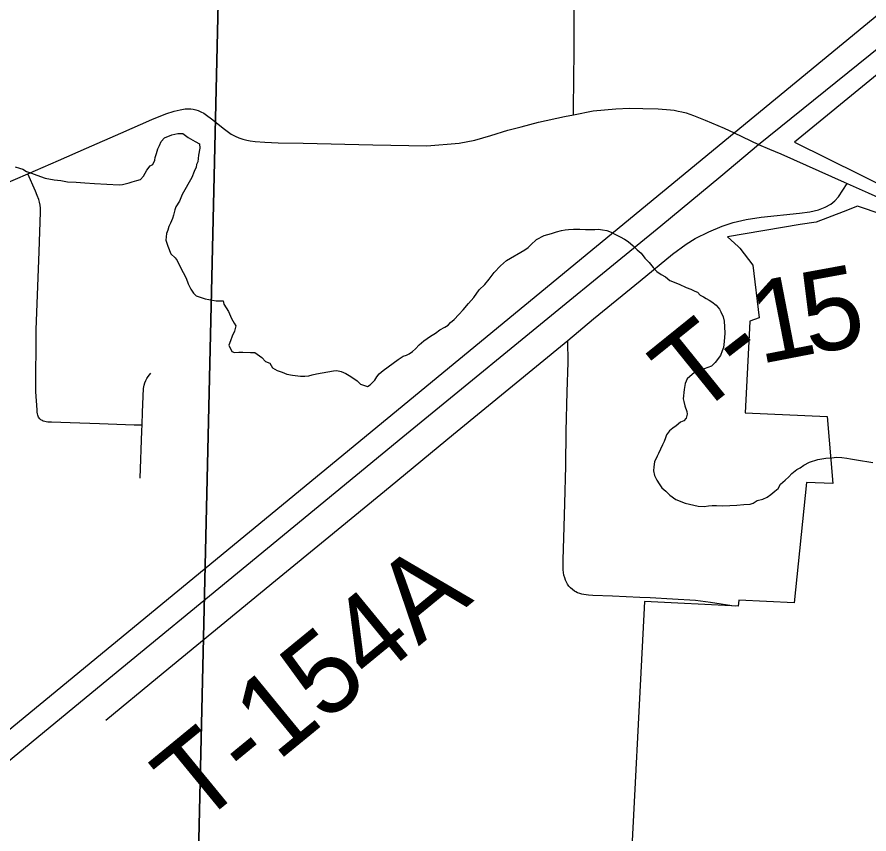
# Model space of a CAD drawing. Extents: x 2.4 to 73.1, y 4.5 to 25.6.
# Drawn here: x 34.9914 to 35.2878, y 22.6553 to 22.9395 of the extents above; entities that cross this region are included whole.
import ezdxf

# ---------------------------------------------------------------- set-up
doc = ezdxf.new("R2010")
doc.units = 0
for name, color, linetype in [('GM_X_Corporation', 7, 'Continuous'), ('GM_X_Minor_River', 7, 'Continuous'), ('GM_X_Section', 7, 'Continuous'), ('GM_X_Township_Road', 7, 'Continuous'), ('GM_X_Township_Road_Text', 7, 'Continuous'), ('GM_X_US_Route', 7, 'Continuous')]:
    doc.layers.add(name, color=color, linetype=linetype)

msp = doc.modelspace()

# ---------------------------------------------------------------- linework, layer by layer
at = {"layer": 'GM_X_Corporation'}
for points in [[(35.29059, 22.91944), (35.26186, 22.89598), (35.33054, 22.86195)], [(35.30132, 22.86774), (35.28377, 22.87371), (35.27879, 22.87177), (35.2694, 22.86809), (35.26388, 22.86727), (35.23852, 22.86307), (35.24226, 22.85961), (35.24281, 22.85911), (35.24742, 22.85311), (35.24962, 22.83487), (35.24632, 22.83373), (35.24607, 22.82887), (35.24471, 22.8018), (35.27327, 22.80056), (35.27521, 22.77718), (35.26598, 22.77751), (35.26172, 22.73566), (35.24248, 22.73661), (35.2423, 22.73449), (35.20964, 22.73611), (35.20424, 22.63033)]]:
    msp.add_lwpolyline(points, dxfattribs=at)
at = {"layer": 'GM_X_Minor_River'}
for points in [[(35.01841, 22.88152), (35.02695, 22.88112), (35.02809, 22.88128), (35.02905, 22.88144), (35.03038, 22.88179), (35.03153, 22.88214), (35.03307, 22.88267), (35.0344, 22.88302), (35.03538, 22.88413), (35.03657, 22.88619), (35.03775, 22.88768), (35.03871, 22.88822), (35.03932, 22.88973), (35.03953, 22.89067), (35.03995, 22.89199), (35.04037, 22.89369), (35.04097, 22.89481), (35.04157, 22.89613), (35.04274, 22.89743), (35.04524, 22.8985), (35.04734, 22.89902), (35.04905, 22.89898), (35.05091, 22.8976), (35.05335, 22.89621), (35.05485, 22.89541), (35.055, 22.89389), (35.05456, 22.89143), (35.05431, 22.88916), (35.05391, 22.88822), (35.05369, 22.88728), (35.05308, 22.88577), (35.05227, 22.8837), (35.04889, 22.87771), (35.04789, 22.87546), (35.0467, 22.8734), (35.04629, 22.87246), (35.04587, 22.87057), (35.04546, 22.86944), (35.04485, 22.86775), (35.04425, 22.86663), (35.04383, 22.86531), (35.04343, 22.86418), (35.04318, 22.86191), (35.04389, 22.8598), (35.04496, 22.85711), (35.04644, 22.85575), (35.04718, 22.85478), (35.0479, 22.85305), (35.04916, 22.85055), (35.05025, 22.84862), (35.05097, 22.84671), (35.05187, 22.84479), (35.05278, 22.84343), (35.05371, 22.84246), (35.05691, 22.84143), (35.06069, 22.84076), (35.06316, 22.8407), (35.06332, 22.83956), (35.06497, 22.83705), (35.06605, 22.83455), (35.06696, 22.83301), (35.0675, 22.83205), (35.06707, 22.83016), (35.06627, 22.82847), (35.06566, 22.82678), (35.06505, 22.82527), (35.06614, 22.82316), (35.06708, 22.82275), (35.0686, 22.8229), (35.06993, 22.82287), (35.07259, 22.8228), (35.07411, 22.82276), (35.07653, 22.82099), (35.07783, 22.81963), (35.07933, 22.81902), (35.08024, 22.81748), (35.08193, 22.81649), (35.08362, 22.81588), (35.08532, 22.81526), (35.0872, 22.81484), (35.09005, 22.81457), (35.09156, 22.81454), (35.0929, 22.81469), (35.09405, 22.81504), (35.09557, 22.81538), (35.10149, 22.81637), (35.10263, 22.81653), (35.10414, 22.81612), (35.10583, 22.8155), (35.10695, 22.81472), (35.10826, 22.81392), (35.10976, 22.81294), (35.11087, 22.81177), (35.11332, 22.81095), (35.11428, 22.81149), (35.11584, 22.81316), (35.11663, 22.81428), (35.11742, 22.8154), (35.11877, 22.81651), (35.12051, 22.81779), (35.12226, 22.81907)], [(34.99083, 22.88735), (34.99234, 22.88693), (34.99347, 22.88652), (34.99478, 22.88573), (34.99647, 22.88512), (34.99835, 22.8845), (35.00118, 22.88348), (35.00439, 22.88283), (35.00666, 22.88258), (35.00893, 22.88214), (35.01197, 22.88207), (35.015, 22.8818), (35.01841, 22.88152)], [(35.12226, 22.81907), (35.124, 22.82036), (35.12574, 22.82146), (35.12688, 22.82181), (35.12785, 22.82235), (35.129, 22.82308), (35.12998, 22.82401), (35.13134, 22.82549), (35.1329, 22.82678), (35.13522, 22.82843), (35.13695, 22.82953), (35.1385, 22.83063), (35.14023, 22.83153), (35.14139, 22.83226), (35.14217, 22.83319), (35.14353, 22.8343), (35.14509, 22.83597), (35.14665, 22.83764), (35.14842, 22.83987), (35.15037, 22.84191), (35.15214, 22.84453), (35.15409, 22.84638), (35.15566, 22.84823), (35.15743, 22.85066), (35.15957, 22.85288), (35.16171, 22.85473), (35.16807, 22.85855), (35.16923, 22.85928), (35.1702, 22.86021), (35.17215, 22.86206), (35.17484, 22.86351), (35.17733, 22.86421), (35.17905, 22.86473), (35.18077, 22.86526), (35.18211, 22.86541), (35.18325, 22.86558), (35.18496, 22.86572), (35.18724, 22.86566), (35.18914, 22.86562), (35.19104, 22.86557), (35.19237, 22.86554), (35.1937, 22.86569), (35.19502, 22.86547), (35.19654, 22.86524), (35.19804, 22.86463), (35.19954, 22.86383), (35.20123, 22.86303), (35.20273, 22.86223), (35.20404, 22.86144), (35.20571, 22.85988), (35.20719, 22.85851), (35.2085, 22.85734), (35.20978, 22.8556), (35.21126, 22.85404), (35.21274, 22.8523), (35.21403, 22.85093), (35.21553, 22.84995), (35.21703, 22.84915), (35.21851, 22.84778), (35.22171, 22.84656), (35.22415, 22.84536), (35.22584, 22.84475), (35.22716, 22.84415), (35.2281, 22.84374), (35.22902, 22.84277), (35.23015, 22.84217), (35.23108, 22.84158), (35.23221, 22.84098), (35.23314, 22.84039), (35.23463, 22.83921), (35.23574, 22.83785), (35.23628, 22.83689), (35.237, 22.83516), (35.23734, 22.83363), (35.23748, 22.83173), (35.23762, 22.82945), (35.23735, 22.82661), (35.23711, 22.82452), (35.2367, 22.82339), (35.23609, 22.8217), (35.23432, 22.81928), (35.23296, 22.81798), (35.23047, 22.8171), (35.22855, 22.81638), (35.22702, 22.81585), (35.22449, 22.81364), (35.22388, 22.81195), (35.22345, 22.80987), (35.22318, 22.80665), (35.22334, 22.80569), (35.22369, 22.80416), (35.2244, 22.80225), (35.22456, 22.80129), (35.22415, 22.79997), (35.22337, 22.79904), (35.22221, 22.7985), (35.22066, 22.79721), (35.21951, 22.79648), (35.21834, 22.79556), (35.21735, 22.79407), (35.21695, 22.79313)], [(35.21695, 22.79313), (35.21654, 22.79181), (35.21594, 22.79069), (35.21454, 22.78768), (35.21413, 22.78675), (35.21313, 22.78468), (35.2129, 22.78298), (35.21287, 22.78165), (35.2132, 22.77993), (35.21392, 22.77839), (35.21484, 22.77704), (35.21576, 22.77569), (35.21705, 22.77452), (35.21854, 22.77315), (35.22059, 22.77158), (35.22379, 22.77036), (35.22832, 22.76929), (35.23041, 22.76924), (35.23193, 22.76939), (35.23326, 22.76955), (35.23478, 22.76951), (35.23687, 22.76946), (35.23934, 22.76958), (35.24182, 22.76971), (35.24429, 22.76984), (35.24638, 22.76998), (35.24753, 22.77033), (35.24888, 22.77124), (35.25079, 22.77176), (35.25233, 22.77249), (35.25368, 22.7734), (35.25504, 22.7745), (35.2562, 22.77542), (35.257, 22.77692), (35.25856, 22.7784), (35.25992, 22.77951), (35.26089, 22.78062), (35.26264, 22.7821), (35.26379, 22.78264), (35.26514, 22.78355), (35.26707, 22.78465), (35.26994, 22.78552), (35.2728, 22.78602), (35.2749, 22.78616), (35.27642, 22.78631), (35.27832, 22.78626), (35.28002, 22.78603), (35.28134, 22.7858), (35.28342, 22.78537), (35.2891, 22.78447)]]:
    msp.add_lwpolyline(points, dxfattribs=at)
at = {"layer": 'GM_X_Section'}
for points in [[(34.56162, 23.09756), (35.06465, 23.08503), (35.0531, 22.5831), (34.54832, 22.60211)], [(35.06465, 23.08503), (35.56221, 23.08304), (35.55168, 22.57541), (35.0531, 22.5831)]]:
    msp.add_lwpolyline(points, close=True, dxfattribs=at)
at = {"layer": 'GM_X_Township_Road'}
for points in [[(35.18506, 22.91682), (35.18518, 22.92862), (35.18525, 22.96188), (35.18557, 23.00166), (35.18574, 23.0119), (35.186, 23.01653), (35.18634, 23.02056), (35.18663, 23.02257), (35.187, 23.02459), (35.18741, 23.0264), (35.18782, 23.02794), (35.18831, 23.02975), (35.18901, 23.03177), (35.18987, 23.03394), (35.19094, 23.03623), (35.19184, 23.03808), (35.19274, 23.03952), (35.194, 23.04138), (35.19625, 23.0447), (35.19924, 23.04865), (35.20812, 23.05985), (35.21703, 23.07102), (35.22364, 23.07915)], [(35.185, 22.90552), (35.18503, 22.90873), (35.18506, 22.91682)], [(34.99514, 22.88488), (35.00589, 22.88963), (35.01557, 22.89386), (35.02754, 22.89909), (35.03832, 22.90389), (35.04323, 22.90582), (35.04614, 22.90679), (35.04822, 22.90726), (35.0499, 22.9075), (35.0509, 22.90754), (35.05187, 22.9075), (35.05272, 22.90739), (35.05361, 22.9072), (35.05446, 22.90694), (35.05539, 22.90654), (35.05639, 22.90602), (35.05736, 22.90536), (35.05906, 22.90409), (35.06362, 22.90043), (35.06595, 22.89876), (35.06736, 22.89802), (35.06862, 22.89747), (35.07, 22.89699), (35.07137, 22.89665), (35.07255, 22.89643), (35.07422, 22.89621), (35.0776, 22.89594), (35.08228, 22.89567), (35.09099, 22.89556), (35.11523, 22.89503), (35.13401, 22.89466), (35.14527, 22.89563), (35.15071, 22.89662), (35.15624, 22.8983), (35.16217, 22.90018), (35.16681, 22.90127), (35.17284, 22.90295), (35.18184, 22.90485), (35.185, 22.90552)], [(35.185, 22.90552), (35.19182, 22.9069), (35.19972, 22.90759), (35.20447, 22.90779), (35.20911, 22.90769), (35.21441, 22.90757), (35.21581, 22.90749), (35.21737, 22.90736), (35.21871, 22.90722), (35.22, 22.90704), (35.22144, 22.90677), (35.22272, 22.9065), (35.22412, 22.90612), (35.22676, 22.90527), (35.23079, 22.90366), (35.23735, 22.90082), (35.24084, 22.89915), (35.24929, 22.89511), (35.25319, 22.89352)], [(35.25319, 22.89352), (35.25708, 22.89192), (35.27909, 22.88206), (35.28023, 22.88155)], [(34.90372, 22.84466), (34.90456, 22.84507), (34.92428, 22.85425), (34.94106, 22.86167), (34.95449, 22.86744), (34.96908, 22.87364), (34.98221, 22.87931), (34.99514, 22.88488)], [(34.9996, 22.79948), (34.99932, 22.79972), (34.99895, 22.80032), (34.9988, 22.80067), (34.99867, 22.80102), (34.99855, 22.80144), (34.99845, 22.80205), (34.99838, 22.80287), (34.99799, 22.80912), (34.99809, 22.83062), (34.99908, 22.85797), (34.99936, 22.86481), (34.99961, 22.87163), (34.99956, 22.87294), (34.99943, 22.87399), (34.99927, 22.87507), (34.99903, 22.87601), (34.99848, 22.87735), (34.99785, 22.87893), (34.99514, 22.88488)], [(35.18303, 22.82694), (35.192, 22.83448), (35.20813, 22.84771), (35.21944, 22.85695), (35.22417, 22.86048), (35.22735, 22.86242), (35.23206, 22.86481), (35.23665, 22.86673), (35.24048, 22.86801), (35.24502, 22.86907), (35.25024, 22.8699), (35.26354, 22.87121), (35.26723, 22.8717), (35.27025, 22.87245), (35.27257, 22.87333), (35.27447, 22.87439), (35.27592, 22.87556), (35.27717, 22.87694), (35.27871, 22.87927), (35.28023, 22.88155)], [(35.28023, 22.88155), (35.28743, 22.87834), (35.30511, 22.87046), (35.31812, 22.86467), (35.32985, 22.85955), (35.3303, 22.85934)], [(35.02231, 22.69482), (35.04028, 22.70965), (35.08131, 22.74343), (35.09984, 22.75858), (35.12117, 22.77617), (35.14324, 22.79435), (35.18303, 22.82694)], [(35.2116, 22.73744), (35.20811, 22.73757), (35.19851, 22.73796), (35.19169, 22.7382), (35.19016, 22.73832), (35.18939, 22.7384), (35.18862, 22.73855), (35.18783, 22.73874), (35.18714, 22.73894), (35.18643, 22.7392), (35.18575, 22.73952), (35.1853, 22.73979), (35.18465, 22.7403), (35.18391, 22.74093), (35.1834, 22.7415), (35.18295, 22.74215), (35.18255, 22.74283), (35.18223, 22.74353), (35.18194, 22.74432), (35.18168, 22.74531), (35.18152, 22.74619), (35.18142, 22.74716), (35.18135, 22.75058), (35.18176, 22.7621), (35.18192, 22.77019), (35.18228, 22.78326), (35.18249, 22.79539), (35.18281, 22.80909), (35.18308, 22.81935), (35.18303, 22.82694)], [(35.03495, 22.79757), (35.03506, 22.80205), (35.03545, 22.81026), (35.03564, 22.81138), (35.03588, 22.81222), (35.03618, 22.81305), (35.03653, 22.81375), (35.03699, 22.81441), (35.03798, 22.81561)], [(34.9996, 22.79948), (35.00012, 22.79919), (35.00053, 22.79904), (35.00105, 22.7989), (35.00156, 22.7988), (35.00219, 22.7987), (35.0034, 22.79862), (35.00989, 22.7984), (35.02011, 22.79802), (35.03218, 22.79766), (35.03495, 22.79757)], [(35.03422, 22.7791), (35.03489, 22.79553), (35.03495, 22.79757)], [(35.24127, 22.7345), (35.24004, 22.73466), (35.23266, 22.73577), (35.22743, 22.73644), (35.21937, 22.737), (35.2116, 22.73744)]]:
    msp.add_lwpolyline(points, dxfattribs=at)
at = {"layer": 'GM_X_US_Route'}
for points in [[(34.81663, 22.55029), (34.90355, 22.62153), (35.24084, 22.89915), (35.5095, 23.12036), (35.5238, 23.13253), (35.5774, 23.1756), (35.60469, 23.19763), (35.62771, 23.21687), (35.64366, 23.23002), (35.65369, 23.23758), (35.67851, 23.2583), (35.69314, 23.27046)], [(35.18627, 22.84306), (35.18936, 22.84559), (35.21537, 22.86682), (35.23618, 22.8841), (35.24929, 22.89511), (35.29177, 22.92935), (35.34888, 22.9764), (35.37939, 23.00146), (35.39912, 23.0176), (35.42788, 23.04137), (35.43184, 23.04444), (35.4383, 23.04946), (35.44305, 23.05341), (35.44372, 23.05376), (35.44432, 23.05416), (35.44517, 23.05486), (35.45509, 23.06298), (35.47086, 23.07561), (35.49893, 23.09874), (35.52765, 23.12253), (35.53302, 23.12692)], [(34.82386, 22.54531), (34.85669, 22.57226), (34.88555, 22.5959), (34.9086, 22.61486), (35.02141, 22.7077), (35.07138, 22.74874), (35.12561, 22.79341), (35.18627, 22.84306)]]:
    msp.add_lwpolyline(points, dxfattribs=at)

# ---------------------------------------------------------------- texts
at = {"layer": 'GM_X_Township_Road_Text'}
for s, height, rotation, p in [('5', 0.02841, 10.3709, (35.26684, 22.82202)), ('1', 0.02841, 10.9583, (35.24974, 22.81871)), ('T', 0.02841, 38.8974, (35.22726, 22.79975)), ('-', 0.02841, 37.7613, (35.24369, 22.813)), ('T-154A', 0.028409, 39.335, (35.05431, 22.65756))]:
    msp.add_text(s, height=height, rotation=rotation, dxfattribs=at).set_placement(p)

doc.saveas('drawing.dxf')
